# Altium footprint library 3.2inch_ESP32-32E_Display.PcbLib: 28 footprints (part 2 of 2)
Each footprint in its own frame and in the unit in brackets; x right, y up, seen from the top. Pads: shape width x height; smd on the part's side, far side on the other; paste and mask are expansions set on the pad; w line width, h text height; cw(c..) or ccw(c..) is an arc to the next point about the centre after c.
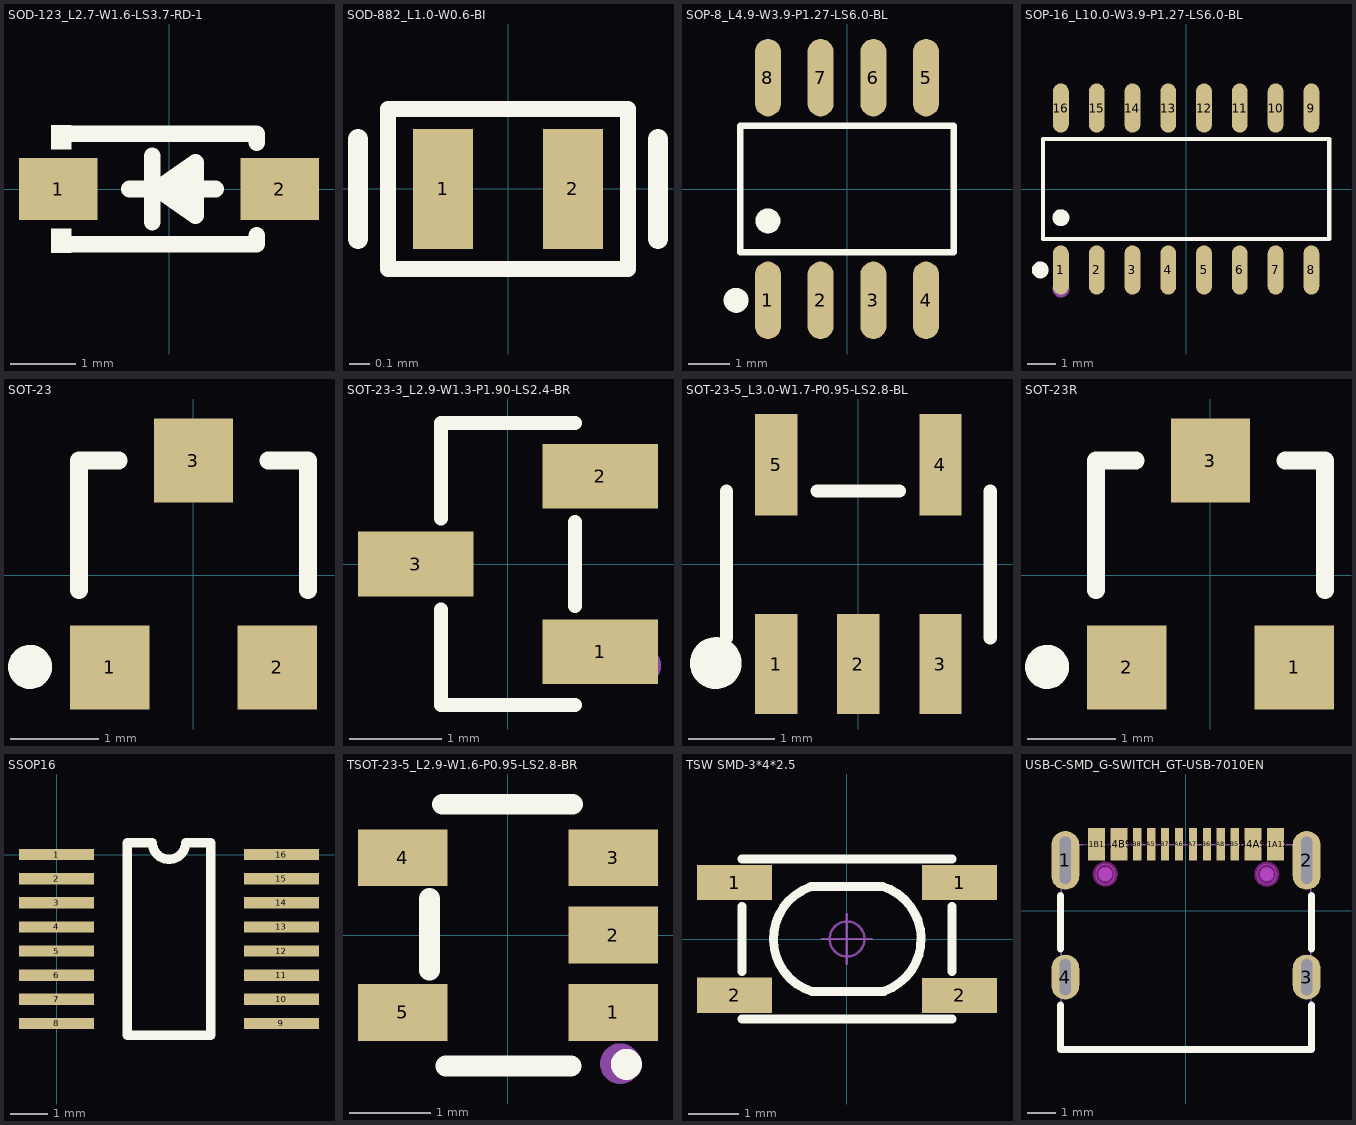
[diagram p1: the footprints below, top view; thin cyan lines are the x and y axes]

## SOD-123_L2.7-W1.6-LS3.7-RD-1 [mm]
pads (2):
  rect 1.2x0.95 smd: 1(-1.7,0) 2(1.7,0)
Top Overlay:
  region: -1.502,-0.977 -1.502,-0.607 -1.806,-0.607 -1.806,-0.977
  region: -1.502,0.977 -1.502,0.607 -1.806,0.607 -1.806,0.977
  region: 0.406,-0.406 0.406,0.406 -0.178,0
  lines w0.254: -1.644,0.849 -1.643,0.85 -1.346,0.85 1.346,0.85 1.346,0.706 ; -1.639,-0.849 -1.638,-0.85 -1.346,-0.85 1.346,-0.85 1.346,-0.706 ; -0.61,0 -0.28,0 ; -0.254,-0.508 -0.254,0.508 ; 0.406,0 0.72,0 ; -0.178,0 0.406,-0.406 0.406,0.406 -0.178,0

## SOD-882_L1.0-W0.6-BI [mm]
pads (2):
  rect 0.3x0.6 smd paste+0 mask+0.05: 1(-0.325,0) 2(0.325,0)
Top Overlay:
  lines w0.08: -0.6,-0.4 -0.6,0.4 0.6,0.4 0.6,-0.4 -0.6,-0.4
  lines w0.1: -0.75,-0.25 -0.75,0.25 ; 0.75,-0.25 0.75,0.25

## SOP-8_L4.9-W3.9-P1.27-LS6.0-BL [mm]
pads (8):
  oval 0.63x1.865 smd: 1(-1.905,-2.682) 2(-0.635,-2.682) 3(0.635,-2.682) 4(1.905,-2.682) 5(1.905,2.682) 6(0.635,2.682) 7(-0.635,2.682) 8(-1.905,2.682)
Top Overlay:
  circle w0.3: c-2.672,-2.682 r0.15
  circle w0.3: c-1.905,-0.769 r0.15
  lines w0.152: -2.576,-1.521 2.576,-1.521 2.576,1.521 -2.576,1.521 -2.576,-1.521

## SOP-16_L10.0-W3.9-P1.27-LS6.0-BL [mm]
pads (16):
  oval 0.56x1.745 smd mask+0.051: 1(-4.445,-2.872) 2(-3.175,-2.872) 3(-1.905,-2.872) 4(-0.635,-2.872) 5(0.635,-2.872) 6(1.905,-2.872) 7(3.175,-2.872) 8(4.445,-2.872) 9(4.445,2.872) 10(3.175,2.872) 11(1.905,2.872) 12(0.635,2.872) 13(-0.635,2.872) 14(-1.905,2.872) 15(-3.175,2.872) 16(-4.445,2.872)
Top Overlay:
  circle w0.3: c-5.177,-2.872 r0.15
  circle w0.3: c-4.445,-1.019 r0.15
  lines w0.152: -5.076,-1.771 5.076,-1.771 5.076,1.771 -5.076,1.771 -5.076,-1.771
Mechanical 6:
  circle w0.3: c-4.445,-3.55 r0.15

## SOT-23 [mm]
pads (3):
  rect 0.9x0.95 smd: 1(-0.95,-1.048) 2(0.95,-1.048) 3(0,1.302)
Top Overlay:
  circle w0.25: c-1.856,-1.041 r0.125
  lines w0.2: -1.3,-0.173 -1.3,1.302 -0.85,1.302 ; 0.85,1.302 1.3,1.302 1.3,-0.173
3D body "SOT-23-3.STEP": height 1.2, standoff 0, extent -1.448,-1.327 1.452,1.473

## SOT-23-3_L2.9-W1.3-P1.90-LS2.4-BR [mm]
pads (3):
  rect 1.25x0.7 smd: 1(1,-0.95) 2(1,0.95) 3(-1,0)
Top Overlay:
  lines w0.152: -0.726,-0.495 -0.726,-1.526 0.726,-1.526 ; -0.726,0.495 -0.726,1.526 0.726,1.526 ; 0.726,-0.455 0.726,0.455
Mechanical 15:
  circle w0.2: c1.46,-1.1 r0.1

## SOT-23-5_L3.0-W1.7-P0.95-LS2.8-BL [mm]
pads (5):
  rect 0.49x1.157 smd: 1(-0.95,-1.154) 2(0,-1.154) 3(0.95,-1.154)
  rect 0.49x1.175 smd: 4(0.95,1.154) 5(-0.95,1.154)
Top Overlay:
  circle w0.3: c-1.651,-1.143 r0.15
  lines w0.152: -1.526,-0.851 -1.526,0.851 ; -0.476,0.851 0.476,0.851 ; 1.526,-0.851 1.526,0.851

## SOT-23R [mm]
pads (3):
  rect 0.9x0.95 smd: 1(0.95,-1.048) 2(-0.95,-1.048) 3(0,1.302)
Top Overlay:
  circle w0.25: c-1.856,-1.041 r0.125
  lines w0.2: -1.3,-0.173 -1.3,1.302 -0.85,1.302 ; 0.85,1.302 1.3,1.302 1.3,-0.173

## SSOP16 [mm]
pads (16):
  rect 2x0.3 smd: 1(0,0) 2(0,-0.643) 3(0,-1.286) 4(0,-1.929) 5(0,-2.572) 6(0,-3.215) 7(0,-3.858) 8(0,-4.501) 9(6,-4.501) 10(6,-3.858) 11(6,-3.215) 12(6,-2.572) 13(6,-1.929) 14(6,-1.286) 15(6,-0.643) 16(6,0)
Top Overlay:
  lines w0.254: 1.889,-4.822 1.889,0.322 2.554,0.322 ccw(c3,0.322) 3.447,0.322 4.111,0.322 4.111,-4.822 1.889,-4.822

## TSOT-23-5_L2.9-W1.6-P0.95-LS2.8-BR [mm]
pads (5):
  rect 1.1x0.7 smd: 1(1.294,-0.951) 2(1.294,-0.001) 3(1.294,0.951) 4(-1.294,0.951) 5(-1.294,-0.949)
Top Overlay:
  circle w0.254: c1.456,-1.589 r0.064
  lines w0.254: -0.966,-0.433 -0.966,0.451 ; -0.806,1.609 0.794,1.609 ; -0.766,-1.609 0.774,-1.609
Mechanical 6:
  circle w0.25: c1.38,-1.58 r0.125

## TSW SMD-3*4*2.5 [mm] "3*4*2.5mm"
height 2.5
pads (4):
  rect 1.5x0.7 smd: 1(-2.25,1.125) 1(2.25,1.125) 2(-2.25,-1.125) 2(2.25,-1.125)
Top Overlay:
  lines w0.178: -2.1,-1.6 2.1,-1.6 ; -2.1,-0.65 -2.1,0.65 ; -2.1,1.6 2.1,1.6 ; -0.738,1.037 ccw(c-0.372,0) -0.7,-1.05 0.737,-1.05 ; -0.725,1.05 0.712,1.05 cw(c0.384,0) 0.75,-1.037 ; 2.1,-0.65 2.1,0.65
Mechanical 15:
  circle w0.05: c0,0 r0.35
  lines w0.05: -0.5,0 0.5,0 ; 0,-0.5 0,0.5

## USB-C-SMD_G-SWITCH_GT-USB-7010EN [mm]
pads (16):
  oval 1x2.1 hole 0.4 slot 1.7 at 90 deg mask+0.05: 1(-4.32,1.802) 2(4.32,1.802)
  oval 1x1.6 hole 0.4 slot 1.3 at 90 deg mask+0.05: 3(4.32,-2.378) 4(-4.32,-2.378)
  rect 0.6x1.15 smd mask+0.05: A1B12(-3.2,2.378) A4B9(-2.4,2.378) B1A12(3.2,2.378) B4A9(2.4,2.378)
  rect 0.3x1.15 smd mask+0.05: A5(-1.25,2.378) A6(-0.25,2.378) A7(0.25,2.378) A8(1.25,2.378) B5(1.75,2.378) B6(0.75,2.378) B7(-0.75,2.378) B8(-1.75,2.378)
Top Overlay:
  lines w0.254: -4.5,-3.386 -4.5,-4.978 4.5,-4.978 4.5,-3.386 ; -4.5,-1.369 -4.5,0.544 ; 4.5,-1.369 4.5,0.544
Top Paste:
  region: 3.82,2.352 3.82,2.452 3.896,2.636 4.037,2.776 4.221,2.852 4.42,2.852 4.603,2.776 4.744,2.636 4.82,2.452 4.82,2.352 4.82,1.252 4.82,1.153 4.744,0.969 4.603,0.829 4.42,0.752 4.221,0.752 4.037,0.829 3.896,0.969 3.82,1.153 3.82,1.252
  region: 3.82,-2.078 3.82,-1.978 3.896,-1.794 4.037,-1.654 4.221,-1.578 4.42,-1.578 4.603,-1.654 4.744,-1.794 4.82,-1.978 4.82,-2.078 4.82,-2.678 4.82,-2.777 4.744,-2.961 4.603,-3.101 4.42,-3.178 4.221,-3.178 4.037,-3.101 3.896,-2.961 3.82,-2.777 3.82,-2.678
  region: -4.82,-2.078 -4.82,-1.978 -4.744,-1.794 -4.603,-1.654 -4.419,-1.578 -4.221,-1.578 -4.037,-1.654 -3.896,-1.794 -3.82,-1.978 -3.82,-2.078 -3.82,-2.678 -3.82,-2.777 -3.896,-2.961 -4.037,-3.101 -4.221,-3.178 -4.419,-3.178 -4.603,-3.101 -4.744,-2.961 -4.82,-2.777 -4.82,-2.678
  region: -4.82,2.352 -4.82,2.452 -4.744,2.636 -4.603,2.776 -4.419,2.852 -4.221,2.852 -4.037,2.776 -3.896,2.636 -3.82,2.452 -3.82,2.352 -3.82,1.252 -3.82,1.153 -3.896,0.969 -4.037,0.829 -4.221,0.752 -4.419,0.752 -4.603,0.829 -4.744,0.969 -4.82,1.153 -4.82,1.252
  region: -3.5,2.952 -2.9,2.952 -2.9,1.802 -3.5,1.802
  region: -2.7,2.952 -2.1,2.952 -2.1,1.802 -2.7,1.802
  region: -1.9,2.952 -1.6,2.952 -1.6,1.802 -1.9,1.802
  region: -1.4,2.952 -1.1,2.952 -1.1,1.802 -1.4,1.802
  region: -0.9,2.952 -0.6,2.952 -0.6,1.802 -0.9,1.802
  region: -0.4,2.952 -0.1,2.952 -0.1,1.802 -0.4,1.802
  region: 0.1,2.952 0.4,2.952 0.4,1.802 0.1,1.802
  region: 0.6,2.952 0.9,2.952 0.9,1.802 0.6,1.802
  region: 1.1,2.952 1.4,2.952 1.4,1.802 1.1,1.802
  region: 1.6,2.952 1.9,2.952 1.9,1.802 1.6,1.802
  region: 2.1,2.952 2.7,2.952 2.7,1.802 2.1,1.802
  region: 2.9,2.952 3.5,2.952 3.5,1.802 2.9,1.802
Keep-Out Layer:
  board cut-out: -2.54,1.302 -2.54,1.372 -2.593,1.501 -2.692,1.599 -2.82,1.652 -2.96,1.652 -3.088,1.599 -3.187,1.501 -3.24,1.372 -3.24,1.302 -3.24,1.233 -3.187,1.104 -3.088,1.006 -2.96,0.952 -2.82,0.952 -2.692,1.006 -2.593,1.104 -2.54,1.233
  board cut-out: 3.24,1.302 3.24,1.372 3.187,1.5 3.088,1.599 2.96,1.652 2.82,1.652 2.692,1.599 2.593,1.5 2.54,1.372 2.54,1.302 2.54,1.232 2.593,1.104 2.692,1.005 2.82,0.952 2.96,0.952 3.088,1.005 3.187,1.104 3.24,1.232
Keep-Out Layer:
  circle w0.1: c2.893,1.305 r0.4
  circle w0.1: c-2.89,1.307 r0.4
Mechanical 1:
  circle w0.005: c-2.89,1.302 r0.35
  circle w0.005: c2.89,1.302 r0.35
Mechanical 6:
  circle w0.25: c2.89,1.302 r0.125
  circle w0.25: c-2.89,1.302 r0.125
Mechanical 15:
  region: -4.41,2.597 -4.41,2.622 -4.445,2.657 -4.495,2.657 -4.53,2.622 -4.53,2.597 -4.53,2.572 -4.495,2.537 -4.445,2.537 -4.41,2.572
  region: 4.17,-1.978 4.47,-1.978 4.47,-2.778 4.17,-2.778
  region: -4.47,-1.978 -4.17,-1.978 -4.17,-2.778 -4.47,-2.778
  region: -4.47,2.352 -4.17,2.352 -4.17,1.252 -4.47,1.252
  region: 4.17,2.352 4.47,2.352 4.47,1.252 4.17,1.252
  region: 1.65,2.597 1.85,2.597 1.85,1.847 1.65,1.847
  region: 1.15,2.597 1.35,2.597 1.35,1.847 1.15,1.847
  region: 0.65,2.597 0.85,2.597 0.85,1.847 0.65,1.847
  region: 0.15,2.597 0.35,2.597 0.35,1.847 0.15,1.847
  region: -0.35,2.597 -0.15,2.597 -0.15,1.847 -0.35,1.847
  region: -0.85,2.597 -0.65,2.597 -0.65,1.847 -0.85,1.847
  region: -1.35,2.597 -1.15,2.597 -1.15,1.847 -1.35,1.847
  region: -1.85,2.597 -1.65,2.597 -1.65,1.847 -1.85,1.847
  region: 3,2.597 3.4,2.597 3.4,1.847 3,1.847
  region: 2.2,2.597 2.6,2.597 2.6,1.847 2.2,1.847
  region: -2.6,2.597 -2.2,2.597 -2.2,1.847 -2.6,1.847
  region: -3.4,2.597 -3,2.597 -3,1.847 -3.4,1.847
  lines w0.051: -4.47,-4.983 4.47,-4.983 4.47,2.367 -4.47,2.367 -4.47,-4.983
